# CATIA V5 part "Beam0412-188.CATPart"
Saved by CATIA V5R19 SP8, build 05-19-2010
Part number: Beam0412-188
Definition: Beam0412-188
Nomenclature: 60721
Material "Aluminium": density 2710 kg/m3, Young's modulus 7e+10 Pa, Poisson ratio 0.346, thermal expansion 2.36e-05 1/K
Bounding box of the stored display mesh (mm): x 0 to 4, y -94 to 94, z -6 to 6
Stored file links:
  D:\Documents\1_Travail\1 - ac-limoges.fr\ac-limoges.fr\Emmanuel Maynard - STI2D_Turgot\1 - IT-I2D\Activités_IT_Première\IT_3_Abris_bus\Maquettes numériques\Abribus_eleve\Beam0412-188.CATPart
  D:\Documents\1_Travail\2- 2I2D\6 -  Ressources ITEC\Ressources Techniques\0-Maquettes numériques_Composants\Catalogue_Makeblock\Catalog_Makeblock\01_Profilés\Table_Beam0412.xls
  C:\Program Files\Dassault Systemes\B19\win_b64\startup\materials\French\Catalog.CATMaterial
  D:\Documents\1_Travail\2- 2I2D\6 -  Ressources ITEC\Ressources Techniques\0-Maquettes numériques_Composants\Catalogue_Makeblock\Catalog_Makeblock\01_Profilés\Table_Beam0412.txt
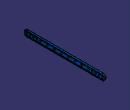
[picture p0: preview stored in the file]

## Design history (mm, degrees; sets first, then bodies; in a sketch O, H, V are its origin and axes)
Parameters
  Longueur = 188 mm
  Nb_Trous_8 = 5
  Nb_Trous_16 = 6
  Trous_16 = true
  `Désignation` = "Beam0412-188"
  `Référence` = "60721"
  L5 = false
  L2 = false
AxisSystem1: origin (0, 0, 0), X (1, 0, 0), Y (0, 1, 0), Z (0, 0, 1)
Body1 (main body), material "Aluminium"
  Sketch1 on YZ plane of AxisSystem1, origin (0, 0, 0), H (0, 1, 0), V (0, 0, 1)
    construction line L1 (-88, 0) -> (88, 0)
    point P1 (-88, 0)
    point P2 (88, 0)
    line L2 (0, 6) -> (88, 6)
    line L3 (88, -6) -> (0, -6)
    arc A1 centre (88, 0) radius 6 from (88, 6) to (88, -6) cw
    line L4 (0, 6) -> (0, -6)
    reference intersected line E1 through (0, 0) direction (0, 1) from ZX plane of AxisSystem1
    distance L1 L2 = 6
    distance P2 L4 = 88 {= Longueur/2 -6mm}
    coincidence: P1 H, L4 E1
    horizontal: L1 H, L3 H
    tangency: A1 L2, A1 L3
    equidistance: P2 P1 O
    vertical: L4 V
  Pad1: profile Sketch1, direction (1, 0, 0), length 4
  Sketch2 on face of Pad1 from Sketch1.L4, origin (0, 0, 0), H (1, 0, 0), V (0, 0, 1)
    point P1 (3.5, 0)
    line L1 (4, 4) -> (4, -4)
    line L2 (4, -4) -> (3, -4)
    line L3 (3, -4) -> (3, 4)
    line L4 (3, 4) -> (4, 4)
    reference intersected line E1 (4, 5.92) -> (4, -5.92) from end face of Pad1
    reference intersected line E2 (4, 6) -> (4, -6) from end face of Pad1
    distance L2 L4 = 8
    distance L3 E2 = 1
    coincidence: P1 H, L1 E1
    vertical: L1 V, L3 V
    horizontal: L2 H, L4 H
    equidistance: L1 L3 P1, L2 L4 P1
  Pocket1: profile Sketch2, direction (0, 1, 0), through (limit type 3)
  Sketch3 on face of Pocket1, origin (3, 73.4934, 0.747), H (0, 1, 0), V (0, 0, 1)
    point P1 (14.5066, -0.747)
    reference intersected line E1 through (0, -0.747) direction (-1, 0) from XY plane of AxisSystem1
    reference projected point E2 (14.5066, -0.747) from axis of face of Pad1 from Sketch1.A1
    coincidence: P1 E1, P1 E2
  Hole1: placed by Sketch3, at (3, 88, 0) direction (-1, 0, 0), diameter 4.1, through (limit type 3)
  RectPattern1: of Hole1, direction 1 instances 5 {= Nb_Trous_8}, spacing 8, along edge [face of Pocket1 from Sketch2.L4 | end face of Pad1] reversed
  Mirror1: of the body so far, about face of Pad1 from Sketch1.L4
  Sketch4 on face of Pocket1 from Sketch2.L3, origin (3, 42.7197, 0.1934), H (0, 1, 0), V (0, 0, 1)
    point P1 (-2.7197, -0.1934)
    reference projected point E1 (-42.7197, -0.1934) from vertex [YZ plane of AxisSystem1 | ZX plane of AxisSystem1 | XY plane of AxisSystem1]
    reference intersected line E2 through (0, -0.1934) direction (-1, 0) from XY plane of AxisSystem1
    distance E1 P1 = 40 {= (Longueur /2)-((Nb_Trous_8-1) *8mm)-22mm}
    coincidence: P1 E2
  Hole2: placed by Sketch4, at (3, 40, 0) direction (-1, 0, 0), diameter 4.1, through (limit type 3)
  RectPattern2: of Hole2, direction 1 instances 6 {= Nb_Trous_16}, spacing 16, along edge [face of Pocket1 from Sketch2.L4 | end face of Pad1] reversed
  Sketch5 on face of Pocket1, origin (3, 0, 0), H (0, 1, 0), V (0, 0, 1)
    circle A1 centre (-72, 0) radius 4
    point P1 (-72, 0)
    reference projected point E1 (-72, 0) from axis of face of Mirror1
    radius A1 = 4
    coincidence: P1 H
    concentricity: A1 E1
  Pocket2: profile Sketch5, direction (-1, 0, 0), through (limit type 3), deactivated
  Sketch6 on face of Pocket1, origin (3, 0, 0), H (0, 1, 0), V (0, 0, 1)
    circle A1 centre (88, 0) radius 4
    point P1 (88, 0)
    circle A2 centre (-80, 0) radius 4
    point P2 (-80, 0)
    reference projected point E1 (88, 0) from axis of face of Hole1
    reference projected point E2 (-80, 0) from axis of face of Mirror1
    radius A1 = 4
    radius A2 = 4
    coincidence: P1 H, P2 H
    concentricity: E1 A1, A2 E2
  Pocket3: profile Sketch6, direction (-1, 0, 0), through (limit type 3), deactivated
Relations
  RectPattern2.Activity = Trous_16
  Hole2.Activity = Trous_16
  Pocket2.Activity = L5
  Sketch6.Activity = L2
  Pocket3.Activity = L2
  Sketch5.Activity = L5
